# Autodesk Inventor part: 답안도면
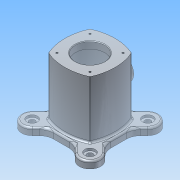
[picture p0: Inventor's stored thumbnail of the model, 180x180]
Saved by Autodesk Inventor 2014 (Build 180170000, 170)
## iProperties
Created: 2016-05
Part Number: 답안도면
Material: 알루미늄 6061
Document SubType Name: Modeling
Designer: net
Density: 2.71 g/cm^3
Appearance: 알루미늄 - 평지
Mass: 1113.6 g
Surface Area: 864.872 cm^2
Volume: 410.921 cm^3
Author: net
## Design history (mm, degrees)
sketch "스케치1"
  geometry: L1 (-43, -43)-(43, 43); L2 (0, 0)-(50, 0); L3 (-2.165, -2.165)-(47.835, -2.165); L4 (-1.189, 0)-(48.811, 0); L5 (0, 0)-(50, 0); A1 r 85.579 centre (42.579, 0) between (-35.355, 35.355) and (-35.355, -35.355); A2 r 85.579 centre (0, -42.579) between (35.355, 35.355) and (-35.355, 35.355); A3 r 85.579 centre (-42.579, 0) between (35.355, -35.355) and (35.355, 35.355); A4 r 85.579 centre (0, 42.579) between (-35.355, -35.355) and (35.355, -35.355)
  constraints: 10 end point, 8 point on circle, 4 centre point, 4 horizontal, 1 midpoint, 1 point on line
  dimensions: "d5" = 50 distance of L2.start A2.start; "d13" = 50 distance of L2.start A3.start; "d14" = 50 distance of L2.start A1.start
extrude "돌출1" new body sketch "스케치1" stored distance "d15" = 98; taper "d16" = 0 deg
sketch "스케치3"
  geometry: L1 (-23.544, -49)-(23.544, -49); L2 (49, -23.544)-(49, 23.544); L3 (-23.544, 49)-(-36.701, 62.157); L4 (-49, 23.544)-(-62.157, 36.701); L5 (-49, -23.544)-(-62.157, -36.701); L6 (-23.544, -49)-(-36.701, -62.157); L7 (23.544, -49)-(36.701, -62.157); L8 (49, -23.544)-(62.157, -36.701); L9 (49, 23.544)-(62.157, 36.701); L10 (23.544, 49)-(36.701, 62.157); L11 (-49, 23.544)-(-49, -23.544); L12 (23.544, 49)-(-23.544, 49); L13 (61.728, -36.272)-(49, -23.544); L14 (36.272, -61.728)-(23.544, -49); A1 r 18 centre (-49.429, 49.429) between (-36.701, 62.157) and (-62.157, 36.701); A2 r 18 centre (-49.429, -49.429) between (-62.157, -36.701) and (-36.701, -62.157); A3 r 18 centre (49.429, -49.429) between (36.701, -62.157) and (62.157, -36.701); A4 r 18 centre (49.429, 49.429) between (62.157, 36.701) and (36.701, 62.157); 2 further points
  constraints: 28 end point, 8 point on circle, 4 centre point, 2 parallel, 1 horizontal, 1 perpendicular, 33 other
  dimensions: "d33" = 360 deg dimension on point (0, 0) L3.start (derived)
extrude "돌출3" join sketch "스케치3" distance "d34" = 12; taper "d35" = 0 deg
sketch "스케치4"
  geometry: C1 r 25 at (0, 0); 1 further point
  constraints: 1 centre point, 1 coincident
  dimensions: "d36" = 50 diameter of C1
extrude "돌출4" cut sketch "스케치4" distance "d37" = 12; taper "d38" = 0 deg
sketch "스케치5"
  geometry: C1 r 25 at (0, 0); 1 further point
  constraints: 1 centre point, 1 coincident
  dimensions: "d39" = 50 diameter of C1
extrude "돌출5" cut sketch "스케치5" distance "d40" = 12; taper "d41" = 0 deg
sketch "스케치6"
  geometry: C1 r 35 at (0, 0); 1 further point
  constraints: 1 centre point, 1 coincident
  dimensions: "d42" = 70 diameter of C1
extrude "돌출6" cut sketch "스케치6" distance "d43" = 37; taper "d45" = 0 deg; dims "d44" = 49, "d46" = 0
node "작업 평면1"
sketch "스케치7"
  geometry: L1 (35.355, 49)-(-35.355, 49) reference; C1 r 20 at (0, 0); 1 further point
  constraints: 1 centre point, 1 coincident
  dimensions: "d48" = 40 diameter of C1
extrude "돌출7" join sketch "스케치7" stored distance "d49" = 37; taper "d50" = 0 deg
sketch "스케치8"
  geometry: C1 r 20 at (0, 0) reference; C2 r 15 at (0, 0)
  constraints: 1 centre point, 1 coincident
  dimensions: "d51" = 30 diameter of C2
extrude "돌출8" cut sketch "스케치8" distance "d52" = 8; taper "d53" = 0 deg
sketch "스케치9"
  geometry: C1 r 15 at (0, 0) reference; C2 r 12.5 at (0, 0)
  constraints: 1 centre point, 1 coincident
  dimensions: "d54" = 25 diameter of C2
extrude "돌출9" cut sketch "스케치9" distance "d55" = 30; taper "d56" = 0 deg
feature "면 기울기1" dims angle "d57" = 10 deg
sketch "스케치11"
  geometry: L1 (0, 0)-(40, 0); C1 r 25 at (0, 0) reference; 4 further points
  constraints: 2 end point, 1 horizontal, 5 other
  dimensions: "d70" = 360 deg dimension on L1.start point (-28.284, 28.284) (derived)
hole "구멍2" sketch "스케치11" at (-28.284, 28.284), (28.284, 28.284), (28.284, -28.284), (-28.284, -28.284) diameter "d72" = 3.242; stored, may be unused: countersink angle "d76" = 90 deg, drill point angle "d78" = 118 deg; dims "d73" = 7, "d74" = 18, "d75" = 4, "d77" = 10
sketch "스케치12"
  geometry: L1 (0, 0)-(40, 0); C1 r 25 at (0, 0) reference; 5 further points
  constraints: 2 coincident, 2 end point, 1 horizontal, 5 other
  dimensions: "d84" = 360 deg dimension on C1.centre point (-28.284, 28.284) (derived)
hole "구멍3" sketch "스케치12" at (28.284, 28.284), (28.284, -28.284), (-28.284, -28.284), (-28.284, 28.284) diameter "d86" = 3.242; stored, may be unused: countersink angle "d90" = 90 deg, drill point angle "d92" = 118 deg; dims "d87" = 7, "d88" = 18, "d89" = 4, "d91" = 10
node "작업 평면2"
sketch "스케치13"
  geometry: L1 (0, 0)-(29, 0); L2 (35.355, 49)-(-35.355, 49) reference; L3 (-25.998, 20.739)-(-25.998, -20.739); L4 (-25.998, -20.739)-(-32.002, -20.739); L5 (-32.002, -20.739)-(-32.002, 20.739); L6 (-32.002, 20.739)-(-25.998, 20.739); 1 further point
  constraints: 2 end point, 1 horizontal, 3 other
  dimensions: "d96" = 41.47897 distance of L3.start L3.end; "d97" = 6.00407 distance of L3.end L4.end; "d98" = 20.73948 vertical distance of L4.end point (-29, 0) (= 0.5 x d96); "d99" = 3.00204 horizontal distance of point (-29, 0) L4.end (= 0.5 x d97)
feature "엠보싱1" sketch "스케치13" dims "d33" = 360 deg (derived), "d100" = 0.5, "d101" = 0
fillet "모깎기1" dims "d102" = 3
fillet "모깎기2" dims "d103" = 3
chamfer "모따기1" distance "d104" = 1; stored, may be unused: second distance "d105" = 2, angle "d106" = 45 deg
fillet "모깎기3" dims "d107" = 3
node "작업 평면3"
sketch "스케치17"
  geometry: L1 (0, 46)-(24.787, 46) reference; L2 (24.787, 46)-(38.823, 60.036) reference; L3 (60.036, 38.823)-(46, 24.787) reference; L4 (46, 24.787)-(46, 0) reference; L5 (24.787, -46)-(0, -46) reference; L6 (38.823, -60.036)-(24.787, -46) reference; L7 (46, -24.787)-(60.036, -38.823) reference; L8 (46, 0)-(46, -24.787) reference; L9 (-46, 0)-(-46, 24.787) reference; L10 (-46, 24.787)-(-60.036, 38.823) reference; L11 (-38.823, 60.036)-(-24.787, 46) reference; L12 (-24.787, 46)-(0, 46) reference; L13 (0, -46)-(-24.787, -46) reference; L14 (-24.787, -46)-(-38.823, -60.036) reference; L15 (-60.036, -38.823)-(-46, -24.787) reference; L16 (-46, -24.787)-(-46, 0) reference; L17 (0, 0)-(49.497, -49.497); L18 (0, 0)-(70, 0); C1 r 32 at (0, 0) reference; C2 r 25 at (0, 0) reference; A1 r 6 centre (33.083, 33.083) between (38.581, 35.487) and (35.487, 38.581) reference; A2 r 88.579 centre (0, -42.579) between (35.487, 38.581) and (0, 46) reference; A3 r 15 centre (49.429, 49.429) between (60.036, 38.823) and (38.823, 60.036) reference; A4 r 88.579 centre (-42.579, 0) between (38.581, -35.487) and (46, 0) reference; A5 r 6 centre (33.083, -33.083) between (35.487, -38.581) and (38.581, -35.487) reference; A6 r 88.579 centre (0, 42.579) between (0, -46) and (35.487, -38.581) reference; A7 r 15 centre (49.429, -49.429) between (38.823, -60.036) and (60.036, -38.823) reference; A8 r 88.579 centre (-42.579, 0) between (46, 0) and (38.581, 35.487) reference; A9 r 88.579 centre (0, -42.579) between (0, 46) and (-35.487, 38.581) reference; A10 r 6 centre (-33.083, 33.083) between (-35.487, 38.581) and (-38.581, 35.487) reference; A11 r 88.579 centre (42.579, 0) between (-38.581, 35.487) and (-46, 0) reference; A12 r 15 centre (-49.429, 49.429) between (-38.823, 60.036) and (-60.036, 38.823) reference; A13 r 88.579 centre (0, 42.579) between (-35.487, -38.581) and (0, -46) reference; A14 r 15 centre (-49.429, -49.429) between (-60.036, -38.823) and (-38.823, -60.036) reference; A15 r 88.579 centre (42.579, 0) between (-46, 0) and (-38.581, -35.487) reference; A16 r 6 centre (-33.083, -33.083) between (-38.581, -35.487) and (-35.487, -38.581) reference; 6 further points
  constraints: 4 end point, 2 coincident, 1 equal length, 1 horizontal, 1 perpendicular, 5 other
  dimensions: "d132" = 70 distance of L17.start L17.end; "d133" = 45 deg angle of L17 L18 (derived); "d136" = 360 deg dimension on point (0, 0) point (49.497, -49.497) (derived)
hole "구멍5" sketch "스케치17" at (49.497, 49.497), (-49.497, 49.497), (-49.497, -49.497), (49.497, -49.497) diameter "d138" = 10; stored, may be unused: countersink angle "d142" = 90 deg, drill point angle "d144" = 0 deg; dims "d139" = 6, "d140" = 18, "d141" = 4, "d143" = 30
fillet "모깎기4" dims "d145" = 25
node "솔리드1"
node "절단 모서리 투영2"
other parameters: "d24" = 36, "d47" = 55, "d93" = 55, "d131" = -49
